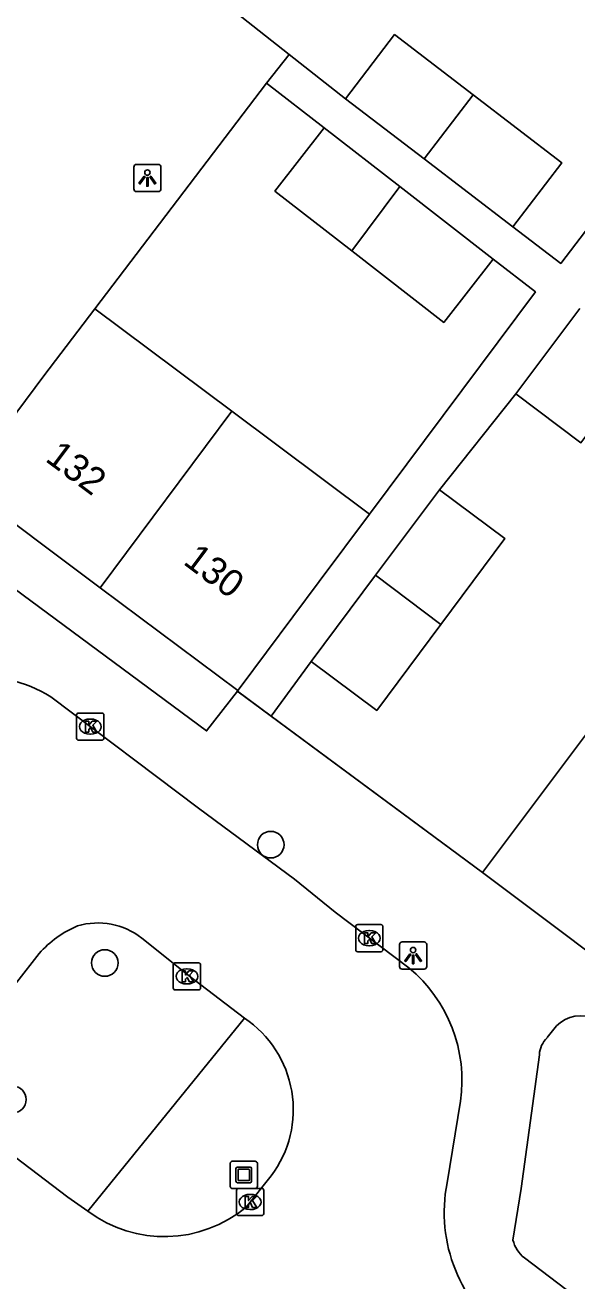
# Model space of a CAD drawing. Extents: x 159040 to 160094, y 381214 to 382518.
# Drawn here: x 159439.83 to 159460.12, y 381904.94 to 381951.1 of the extents above; entities that cross this region are included whole.
import ezdxf

# ---------------------------------------------------------------- set-up
doc = ezdxf.new("R2010")
doc.units = 0
for name, color, linetype in [('IMGEO_Boom', 7, 'Continuous'), ('IMGEO_Groenvoorziening', 7, 'Continuous'), ('IMGEO_Kolk', 7, 'Continuous'), ('IMGEO_Kunstobject', 7, 'Continuous'), ('IMGEO_Lichtpunt', 7, 'Continuous'), ('IMGEO_Muur', 7, 'Continuous'), ('IMGEO_Pand', 7, 'Continuous'), ('IMGEO_Pand_nummerreeks', 7, 'Continuous'), ('IMGEO_Rijbaan_lokaal_open', 7, 'Continuous'), ('IMGEO_Voetpad_open', 7, 'Continuous')]:
    doc.layers.add(name, color=color, linetype=linetype)

msp = doc.modelspace()

# ---------------------------------------------------------------- linework, layer by layer
at = {"layer": 'IMGEO_Boom'}
for centre in [(159448.857, 381920.973), (159442.757, 381916.625), (159439.379, 381911.604)]:
    msp.add_circle(centre, 0.489, dxfattribs=at)
at = {"layer": 'IMGEO_Groenvoorziening'}
msp.add_lwpolyline([(159447.89, 381914.593), (159442.138, 381907.498)], dxfattribs=at)
at = {"layer": 'IMGEO_Kolk'}
for p, q in [((159441.721, 381924.886), (159441.721, 381925.738)), ((159441.796, 381925.812), (159442.648, 381925.812)), ((159442.209, 381925.592), (159442.234, 381925.592)), ((159442.722, 381925.738), (159442.722, 381924.886)), ((159442.232, 381925.032), (159442.207, 381925.032)), ((159442.648, 381924.812), (159441.796, 381924.812)), ((159451.982, 381917.112), (159451.982, 381917.964)), ((159452.057, 381918.038), (159452.909, 381918.038)), ((159452.47, 381917.818), (159452.495, 381917.818)), ((159452.983, 381917.964), (159452.983, 381917.112)), ((159452.493, 381917.258), (159452.468, 381917.258)), ((159452.909, 381917.038), (159452.057, 381917.038)), ((159445.275, 381915.707), (159445.275, 381916.559)), ((159445.35, 381916.633), (159446.202, 381916.633)), ((159445.763, 381916.413), (159445.788, 381916.413)), ((159446.276, 381916.559), (159446.276, 381915.707)), ((159445.786, 381915.853), (159445.761, 381915.853)), ((159446.202, 381915.633), (159445.35, 381915.633)), ((159447.6, 381907.414), (159447.6, 381908.266)), ((159447.675, 381908.34), (159448.527, 381908.34)), ((159448.088, 381908.12), (159448.113, 381908.12)), ((159448.601, 381908.266), (159448.601, 381907.414)), ((159448.111, 381907.56), (159448.086, 381907.56)), ((159448.527, 381907.34), (159447.675, 381907.34))]:
    msp.add_line(p, q, dxfattribs=at)
for points in [[(159441.721, 381924.886), (159441.721, 381925.738)], [(159441.796, 381925.812), (159442.648, 381925.812)], [(159442.042, 381925.512), (159442.165, 381925.512), (159442.165, 381925.361), (159442.295, 381925.512), (159442.459, 381925.512), (159442.313, 381925.361), (159442.466, 381925.112), (159442.314, 381925.112), (159442.229, 381925.276), (159442.165, 381925.209), (159442.165, 381925.112), (159442.042, 381925.112), (159442.042, 381925.512)], [(159442.722, 381925.738), (159442.722, 381924.886)], [(159442.648, 381924.812), (159441.796, 381924.812)], [(159451.982, 381917.112), (159451.982, 381917.964)], [(159452.057, 381918.038), (159452.909, 381918.038)], [(159452.303, 381917.738), (159452.426, 381917.738), (159452.426, 381917.587), (159452.556, 381917.738), (159452.72, 381917.738), (159452.574, 381917.587), (159452.727, 381917.338), (159452.575, 381917.338), (159452.49, 381917.502), (159452.426, 381917.435), (159452.426, 381917.338), (159452.303, 381917.338), (159452.303, 381917.738)], [(159452.983, 381917.964), (159452.983, 381917.112)], [(159452.909, 381917.038), (159452.057, 381917.038)], [(159445.275, 381915.707), (159445.275, 381916.559)], [(159445.35, 381916.633), (159446.202, 381916.633)], [(159445.596, 381916.333), (159445.719, 381916.333), (159445.719, 381916.182), (159445.849, 381916.333), (159446.013, 381916.333), (159445.867, 381916.182), (159446.02, 381915.933), (159445.868, 381915.933), (159445.783, 381916.097), (159445.719, 381916.03), (159445.719, 381915.933), (159445.596, 381915.933), (159445.596, 381916.333)], [(159446.276, 381916.559), (159446.276, 381915.707)], [(159446.202, 381915.633), (159445.35, 381915.633)], [(159447.6, 381907.414), (159447.6, 381908.266)], [(159447.675, 381908.34), (159448.527, 381908.34)], [(159447.921, 381908.04), (159448.044, 381908.04), (159448.044, 381907.889), (159448.174, 381908.04), (159448.338, 381908.04), (159448.192, 381907.889), (159448.345, 381907.64), (159448.193, 381907.64), (159448.108, 381907.804), (159448.044, 381907.737), (159448.044, 381907.64), (159447.921, 381907.64), (159447.921, 381908.04)], [(159448.601, 381908.266), (159448.601, 381907.414)], [(159448.527, 381907.34), (159447.675, 381907.34)]]:
    msp.add_lwpolyline(points, dxfattribs=at)
for centre, start, end in [((159441.798, 381925.736), 91.552, 178.448), ((159441.798, 381925.736), 91.552, 178.448), ((159442.646, 381925.736), 1.552, 88.448), ((159442.646, 381925.736), 1.552, 88.448), ((159441.798, 381924.888), 181.552, 268.448), ((159441.798, 381924.888), 181.552, 268.448), ((159442.646, 381924.888), 271.552, 358.448), ((159442.646, 381924.888), 271.552, 358.448), ((159452.059, 381917.962), 91.552, 178.448), ((159452.059, 381917.962), 91.552, 178.448), ((159452.907, 381917.962), 1.552, 88.448), ((159452.907, 381917.962), 1.552, 88.448), ((159452.059, 381917.114), 181.552, 268.448), ((159452.059, 381917.114), 181.552, 268.448), ((159452.907, 381917.114), 271.552, 358.448), ((159452.907, 381917.114), 271.552, 358.448), ((159445.352, 381916.557), 91.552, 178.448), ((159445.352, 381916.557), 91.552, 178.448), ((159446.2, 381916.557), 1.552, 88.448), ((159446.2, 381916.557), 1.552, 88.448), ((159445.352, 381915.709), 181.552, 268.448), ((159445.352, 381915.709), 181.552, 268.448), ((159446.2, 381915.709), 271.552, 358.448), ((159446.2, 381915.709), 271.552, 358.448), ((159447.677, 381908.264), 91.552, 178.448), ((159447.677, 381908.264), 91.552, 178.448), ((159448.525, 381908.264), 1.552, 88.448), ((159448.525, 381908.264), 1.552, 88.448), ((159447.677, 381907.416), 181.552, 268.448), ((159447.677, 381907.416), 181.552, 268.448), ((159448.525, 381907.416), 271.552, 358.448), ((159448.525, 381907.416), 271.552, 358.448)]:
    msp.add_arc(centre, 0.0765, start, end, dxfattribs=at)
for centre, major_axis, ratio, start_param, end_param in [((159442.208, 381925.312), (-0.387, 0.002), 0.722429, 4.712389, 7.853982), ((159442.233, 381925.312), (-0.39, 0.002), 0.717154, 1.570796, 4.712389), ((159452.469, 381917.538), (-0.387, 0.002), 0.722429, 4.712389, 7.853982), ((159452.494, 381917.538), (-0.39, 0.002), 0.717154, 1.570796, 4.712389), ((159445.762, 381916.133), (-0.387, 0.002), 0.722429, 4.712389, 7.853982), ((159445.787, 381916.133), (-0.39, 0.002), 0.717154, 1.570796, 4.712389), ((159448.087, 381907.84), (-0.387, 0.002), 0.722429, 4.712389, 7.853982), ((159448.112, 381907.84), (-0.39, 0.002), 0.717154, 1.570796, 4.712389)]:
    msp.add_ellipse(centre, major_axis=major_axis, ratio=ratio, start_param=start_param, end_param=end_param, dxfattribs=at)
at = {"layer": 'IMGEO_Kunstobject'}
for p, q in [((159447.366, 381909.252), (159447.366, 381908.411)), ((159447.366, 381909.252), (159447.366, 381908.411)), ((159448.282, 381909.336), (159447.441, 381909.336)), ((159448.282, 381909.336), (159447.441, 381909.336)), ((159447.58, 381908.6), (159447.58, 381909.074)), ((159447.63, 381909.124), (159448.104, 381909.124)), ((159447.66, 381909.024), (159447.66, 381908.65)), ((159448.054, 381909.044), (159447.68, 381909.044)), ((159448.074, 381908.65), (159448.074, 381909.024)), ((159448.154, 381909.074), (159448.154, 381908.6)), ((159448.366, 381908.42), (159448.366, 381909.261)), ((159448.366, 381908.42), (159448.366, 381909.261)), ((159448.104, 381908.55), (159447.63, 381908.55)), ((159447.68, 381908.63), (159448.054, 381908.63)), ((159447.45, 381908.336), (159448.291, 381908.336)), ((159447.45, 381908.336), (159448.291, 381908.336))]:
    msp.add_line(p, q, dxfattribs=at)
for centre, radius, start, end in [((159447.444, 381909.258), 0.0779, 92.4484, 184.2845), ((159447.444, 381909.258), 0.0779, 92.4484, 184.2845), ((159447.63, 381909.074), 0.05, 90, 180), ((159447.68, 381909.024), 0.02, 90, 180), ((159448.054, 381909.024), 0.02, 360, 90), ((159448.104, 381909.074), 0.05, 360, 90), ((159448.288, 381909.258), 0.0779, 2.4484, 94.2845), ((159448.288, 381909.258), 0.0779, 2.4484, 94.2845), ((159447.63, 381908.6), 0.05, 180, 270), ((159447.68, 381908.65), 0.02, 180, 270), ((159448.054, 381908.65), 0.02, 270, 0), ((159448.104, 381908.6), 0.05, 270, 0), ((159448.288, 381908.414), 0.0779, 272.4484, 4.2845), ((159448.288, 381908.414), 0.0779, 272.4484, 4.2845), ((159447.444, 381908.414), 0.0779, 182.4484, 274.2845), ((159447.444, 381908.414), 0.0779, 182.4484, 274.2845)]:
    msp.add_arc(centre, radius, start, end, dxfattribs=at)
at = {"layer": 'IMGEO_Lichtpunt'}
for p, q in [((159443.824, 381945.881), (159443.824, 381945.074)), ((159443.824, 381945.881), (159443.824, 381945.074)), ((159444.726, 381945.976), (159443.918, 381945.976)), ((159444.726, 381945.976), (159443.918, 381945.976)), ((159444.82, 381945.074), (159444.82, 381945.881)), ((159444.82, 381945.074), (159444.82, 381945.881)), ((159443.918, 381944.98), (159444.726, 381944.98)), ((159443.918, 381944.98), (159444.726, 381944.98)), ((159453.596, 381917.302), (159453.596, 381916.495)), ((159453.596, 381917.302), (159453.596, 381916.495)), ((159454.498, 381917.397), (159453.69, 381917.397)), ((159454.498, 381917.397), (159453.69, 381917.397)), ((159454.592, 381916.495), (159454.592, 381917.302)), ((159454.592, 381916.495), (159454.592, 381917.302)), ((159453.69, 381916.401), (159454.498, 381916.401)), ((159453.69, 381916.401), (159454.498, 381916.401))]:
    msp.add_line(p, q, dxfattribs=at)
for points in [[(159444.198, 381945.545), (159444.237, 381945.517), (159444.049, 381945.255), (159444.011, 381945.282), (159444.198, 381945.545)], [(159444.3, 381945.497), (159444.347, 381945.497), (159444.347, 381945.175), (159444.3, 381945.175), (159444.3, 381945.497)], [(159444.41, 381945.517), (159444.448, 381945.544), (159444.635, 381945.282), (159444.596, 381945.254), (159444.41, 381945.517)], [(159453.97, 381916.966), (159454.009, 381916.938), (159453.821, 381916.676), (159453.783, 381916.703), (159453.97, 381916.966)], [(159454.072, 381916.918), (159454.119, 381916.918), (159454.119, 381916.596), (159454.072, 381916.596), (159454.072, 381916.918)], [(159454.182, 381916.938), (159454.22, 381916.965), (159454.407, 381916.703), (159454.368, 381916.675), (159454.182, 381916.938)]]:
    msp.add_lwpolyline(points, dxfattribs=at)
for centre in [(159444.323, 381945.679), (159454.095, 381917.1)]:
    msp.add_circle(centre, 0.0994, dxfattribs=at)
for centre, start, end in [((159443.918, 381945.881), 90, 180), ((159443.918, 381945.881), 90, 180), ((159444.726, 381945.881), 0, 90), ((159444.726, 381945.881), 0, 90), ((159443.918, 381945.074), 180, 270), ((159443.918, 381945.074), 180, 270), ((159444.726, 381945.074), 270, 0), ((159444.726, 381945.074), 270, 360), ((159453.69, 381917.302), 90, 180), ((159453.69, 381917.302), 90, 180), ((159454.498, 381917.302), 0, 90), ((159454.498, 381917.302), 0, 90), ((159453.69, 381916.495), 180, 270), ((159453.69, 381916.495), 180, 270), ((159454.498, 381916.495), 270, 0), ((159454.498, 381916.495), 270, 360)]:
    msp.add_arc(centre, 0.0946, start, end, dxfattribs=at)
at = {"layer": 'IMGEO_Muur'}
msp.add_lwpolyline([(159456.646, 381919.953), (159447.66, 381926.59)], dxfattribs=at)
at = {"layer": 'IMGEO_Pand'}
for points in [[(159451.606, 381948.393), (159453.41, 381950.748), (159456.303, 381948.533)], [(159451.606, 381948.393), (159454.502, 381946.176)], [(159456.303, 381948.533), (159454.502, 381946.176)], [(159456.303, 381948.533), (159459.561, 381946.039), (159457.758, 381943.684)], [(159451.835, 381942.801), (159449.011, 381944.996), (159450.822, 381947.325)], [(159453.601, 381945.165), (159450.822, 381947.325)], [(159454.502, 381946.176), (159457.758, 381943.684)], [(159451.835, 381942.801), (159453.601, 381945.165)], [(159457.033, 381942.498), (159453.601, 381945.165)], [(159457.033, 381942.498), (159455.222, 381940.169), (159451.835, 381942.801)], [(159437.521, 381934.199), (159440.513, 381938.206), (159442.39, 381940.671)], [(159442.39, 381940.671), (159447.431, 381936.906)], [(159460.221, 381940.68), (159457.867, 381937.549)], [(159462.619, 381938.878), (159460.265, 381935.747), (159457.867, 381937.549)], [(159447.431, 381936.906), (159442.585, 381930.419)], [(159447.431, 381936.906), (159452.494, 381933.125)], [(159442.585, 381930.419), (159437.556, 381934.173), (159437.521, 381934.199)], [(159455.064, 381934.019), (159452.716, 381930.874)], [(159455.117, 381929.069), (159457.47, 381932.222), (159455.064, 381934.019)], [(159447.651, 381926.637), (159447.733, 381926.747), (159450.642, 381930.644), (159452.494, 381933.125)], [(159452.716, 381930.874), (159450.349, 381927.703)], [(159452.716, 381930.874), (159455.117, 381929.069)], [(159442.585, 381930.419), (159447.651, 381926.637)], [(159455.117, 381929.069), (159452.756, 381925.906), (159450.349, 381927.703)], [(159456.646, 381919.953), (159460.472, 381925.044)], [(159463.424, 381914.86), (159456.646, 381919.953)]]:
    msp.add_lwpolyline(points, dxfattribs=at)
at = {"layer": 'IMGEO_Rijbaan_lokaal_open'}
for points in [[(159447.567, 381951.57), (159449.536, 381950.021)], [(159448.708, 381948.968), (159449.536, 381950.021)], [(159442.39, 381940.671), (159448.708, 381948.968)], [(159453.939, 381916.441), (159451.222, 381918.488), (159449.736, 381919.701), (159446.207, 381922.318), (159440.766, 381926.404)], [(159444.115, 381917.538), (159445.82, 381916.183), (159447.89, 381914.593)], [(159437.867, 381913.808), (159440.342, 381916.976)], [(159455.343, 381908.543), (159455.833, 381911.541)], [(159442.138, 381907.498), (159441.4, 381908.012), (159438.052, 381910.557)], [(159448.876, 381908.802), (159447.952, 381907.655)]]:
    msp.add_lwpolyline(points, dxfattribs=at)
for centre, radius, start, end in [((159438.289, 381922.53), 4.599, 57.4067, 98.3889), ((159443.339, 381914.286), 4.027, 113.1463, 138.0899), ((159442.5, 381915.487), 2.61, 51.7874, 106.5659), ((159450.548, 381912.314), 5.341, 351.6771, 50.589), ((159445.642, 381911.231), 4.045, 323.0942, 56.2313), ((159460.844, 381907.452), 5.608, 168.7845, 235.306), ((159444.946, 381911.253), 4.688, 233.2113, 309.8824)]:
    msp.add_arc(centre, radius, start, end, dxfattribs=at)
at = {"layer": 'IMGEO_Voetpad_open'}
for points in [[(159457.758, 381943.684), (159459.521, 381942.335), (159465.718, 381950.443)], [(159449.536, 381950.021), (159451.606, 381948.393)], [(159450.822, 381947.325), (159448.708, 381948.968)], [(159452.494, 381933.125), (159458.588, 381941.289), (159457.033, 381942.498)], [(159457.867, 381937.549), (159455.064, 381934.019)], [(159447.631, 381926.611), (159446.5, 381925.157), (159436.632, 381932.453), (159423.238, 381914.788), (159421.82, 381915.982)], [(159450.349, 381927.703), (159448.868, 381925.698)], [(159447.631, 381926.611), (159447.651, 381926.637)], [(159448.868, 381925.698), (159447.631, 381926.611)], [(159456.646, 381919.953), (159448.868, 381925.698)], [(159459.018, 381913.88), (159459.37, 381914.31)], [(159457.764, 381906.44), (159458.066, 381908.341), (159458.737, 381913.254)], [(159460.022, 381904.395), (159458.184, 381905.789)]]:
    msp.add_lwpolyline(points, dxfattribs=at)
for centre, radius, start, end in [((159460.234, 381913.498), 1.186, 61.819, 136.7662), ((159459.703, 381913.196), 0.968, 135.0647, 176.5864), ((159458.931, 381906.732), 1.203, 194.0446, 231.6125)]:
    msp.add_arc(centre, radius, start, end, dxfattribs=at)

# ---------------------------------------------------------------- texts
at = {"layer": 'IMGEO_Pand_nummerreeks'}
for s, rotation, p in [('132', 323.2562, (159440.527, 381935.099)), ('130', 323.2588, (159445.598, 381931.314))]:
    msp.add_text(s, height=1, rotation=rotation, dxfattribs=at).set_placement(p)

doc.saveas('drawing.dxf')
